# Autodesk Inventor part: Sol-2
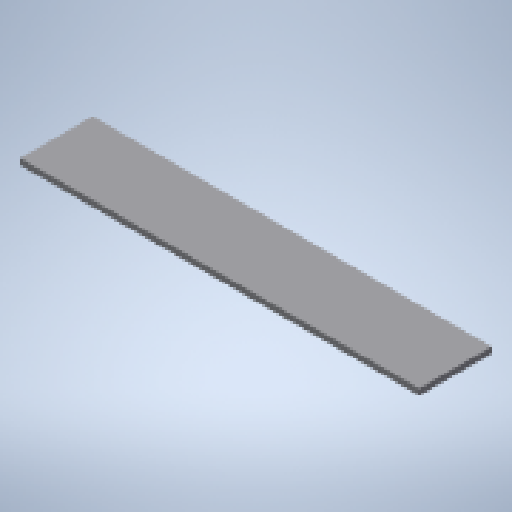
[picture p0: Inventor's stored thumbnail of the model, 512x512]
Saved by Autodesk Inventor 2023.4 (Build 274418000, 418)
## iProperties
Created: 2011-01
Part Number: Sol-2
Document SubType Name: Modeling
Designer: eric
Density: 1 g/cm^3
Material: Générique
Appearance: Par défaut
Author: eric
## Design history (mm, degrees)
sketch "Esquisse1"
  geometry: L1 (-5442.386, -201.223)-(1012.544, -201.223); L2 (1012.544, -201.223)-(1012.544, 970.803); L3 (1012.544, 970.803)-(-5442.386, 970.803); L4 (-5442.386, 970.803)-(-5442.386, -201.223)
  constraints: 8 end point, 2 parallel, 1 horizontal, 1 perpendicular
extrude "Extrusion1" new body sketch "Esquisse1" distance "d0" = 100; taper "d1" = 0 deg
sketch "Esquisse2"
  geometry: L1 (0, 0)-(6454.929, 0) reference; L2 (6454.929, 0)-(6454.929, 100) reference; L3 (0, 0)-(6454.929, 100); L4 (0, 0)-(6454.929, 0); L5 (6454.929, 0)-(6454.929, 100); L6 (0, 0)-(0, 100) reference; L7 (0, 100)-(1.549, 0.024); L8 (0, 100)-(0, 0); 1 further point
  constraints: 10 end point, 3 collinear, 1 perpendicular, 1 point on line
extrude "Extrusion2" cut sketch "Esquisse2" extent not by distance; stored distance "d2" = 10; taper "d3" = 0 deg
node "Solide1"
node "Corps solides"
node "Corps surfaciques"
